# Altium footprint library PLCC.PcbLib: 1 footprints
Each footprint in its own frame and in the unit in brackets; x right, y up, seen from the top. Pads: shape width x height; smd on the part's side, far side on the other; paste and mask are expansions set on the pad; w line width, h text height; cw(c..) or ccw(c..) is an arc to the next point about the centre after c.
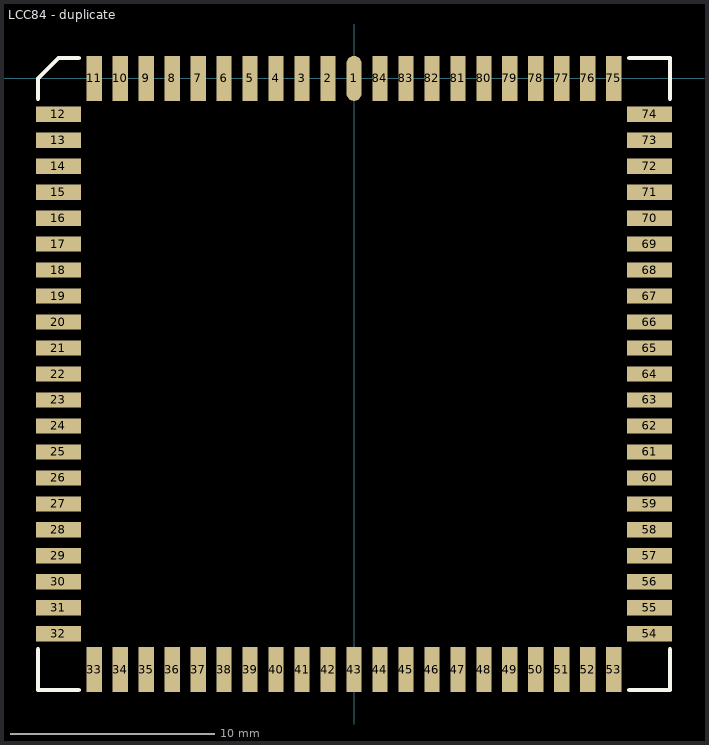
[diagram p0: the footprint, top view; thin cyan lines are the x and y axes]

## LCC84 - duplicate [mm]
pads (84):
  oval 0.75x2.2 smd: 1(0,0)
  rect 0.75x2.2 smd: 2(-1.27,0) 3(-2.54,0) 4(-3.81,0) 5(-5.08,0) 6(-6.35,0) 7(-7.62,0) 8(-8.89,0) 9(-10.16,0) 10(-11.43,0) 11(-12.7,0) 33(-12.7,-28.9) 34(-11.43,-28.9) 35(-10.16,-28.9) 36(-8.89,-28.9) 37(-7.62,-28.9) 38(-6.35,-28.9) 39(-5.08,-28.9) 40(-3.81,-28.9) 41(-2.54,-28.9) 42(-1.27,-28.9) 43(0,-28.9) 44(1.27,-28.9) 45(2.54,-28.9) 46(3.81,-28.9) 47(5.08,-28.9) 48(6.35,-28.9) 49(7.62,-28.9) 50(8.89,-28.9) 51(10.16,-28.9) 52(11.43,-28.9) 53(12.7,-28.9) 75(12.7,0) 76(11.43,0) 77(10.16,0) 78(8.89,0) 79(7.62,0) 80(6.35,0) 81(5.08,0) 82(3.81,0) 83(2.54,0) 84(1.27,0)
  rect 2.2x0.75 smd: 12(-14.45,-1.75) 13(-14.45,-3.02) 14(-14.45,-4.29) 15(-14.45,-5.56) 16(-14.45,-6.83) 17(-14.45,-8.1) 18(-14.45,-9.37) 19(-14.45,-10.64) 20(-14.45,-11.91) 21(-14.45,-13.18) 22(-14.45,-14.45) 23(-14.45,-15.72) 24(-14.45,-16.99) 25(-14.45,-18.26) 26(-14.45,-19.53) 27(-14.45,-20.8) 28(-14.45,-22.07) 29(-14.45,-23.34) 30(-14.45,-24.61) 31(-14.45,-25.88) 32(-14.45,-27.15) 54(14.45,-27.15) 55(14.45,-25.88) 56(14.45,-24.61) 57(14.45,-23.34) 58(14.45,-22.07) 59(14.45,-20.8) 60(14.45,-19.53) 61(14.45,-18.26) 62(14.45,-16.99) 63(14.45,-15.72) 64(14.45,-14.45) 65(14.45,-13.18) 66(14.45,-11.91) 67(14.45,-10.64) 68(14.45,-9.37) 69(14.45,-8.1) 70(14.45,-6.83) 71(14.45,-5.56) 72(14.45,-4.29) 73(14.45,-3.02) 74(14.45,-1.75)
Top Overlay:
  lines w0.2: -15.45,-27.9 -15.45,-29.9 -13.45,-29.9 ; -15.45,-1 -15.45,0 -14.45,1 -13.45,1 ; 13.45,-29.9 15.45,-29.9 15.45,-27.9 ; 13.45,1 15.45,1 15.45,-1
